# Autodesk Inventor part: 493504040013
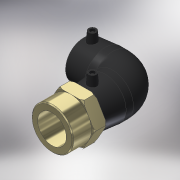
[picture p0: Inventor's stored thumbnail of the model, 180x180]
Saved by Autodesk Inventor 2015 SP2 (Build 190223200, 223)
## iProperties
Created: 2017-06
Part Number: 493504040013
Material: Generic
Description: PLASSON 90° ELBOW FEMALE TRANSITION 40-1.1/4''
Document SubType Name: Modeling
Designer: KIM
Mass: 209.215 g
Surface Area: 509.962 cm^2
Volume: 209.215 cm^3
Density: 1 g/cm^3
Appearance: Rubber - Black
Author: KIM
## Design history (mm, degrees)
derived "493504.ipt"
feature "Solid1::493504.ipt"
tag "TaggingFeature1"
body "Solid1"
other parameters: "d2" = 56, "d4" = 30.66667, "d5" = 50.4, "d8" = 168 deg, "d10" = 17.6, "d11" = 5.86667, "d29" = 47, "d30" = 15, "d31" = 50.6, "d34" = 5 deg, "d41" = 4, "d42" = 14, "d43" = 0, "d48" = 64, "d50" = 34, "d51" = 17.6, "d52" = 44, "d54" = 90 deg, "d58" = 44, "d59" = 0, "d61" = 90 deg, "d86" = 3, "d87" = 0, "d93" = 0.1, "d96" = 38.952, "d97" = 29, "d98" = 25, "d99" = 56, "d108" = 0, "d109" = 1.2, "d112" = 45 deg, "d113" = 45 deg, "d114" = 2, "L_" = 117, "L_1" = 44, "D_" = 29, "A_" = 47, "d_2" = 12, "L_2" = 25, "D_1" = 56, "Rp_" = 38.952
